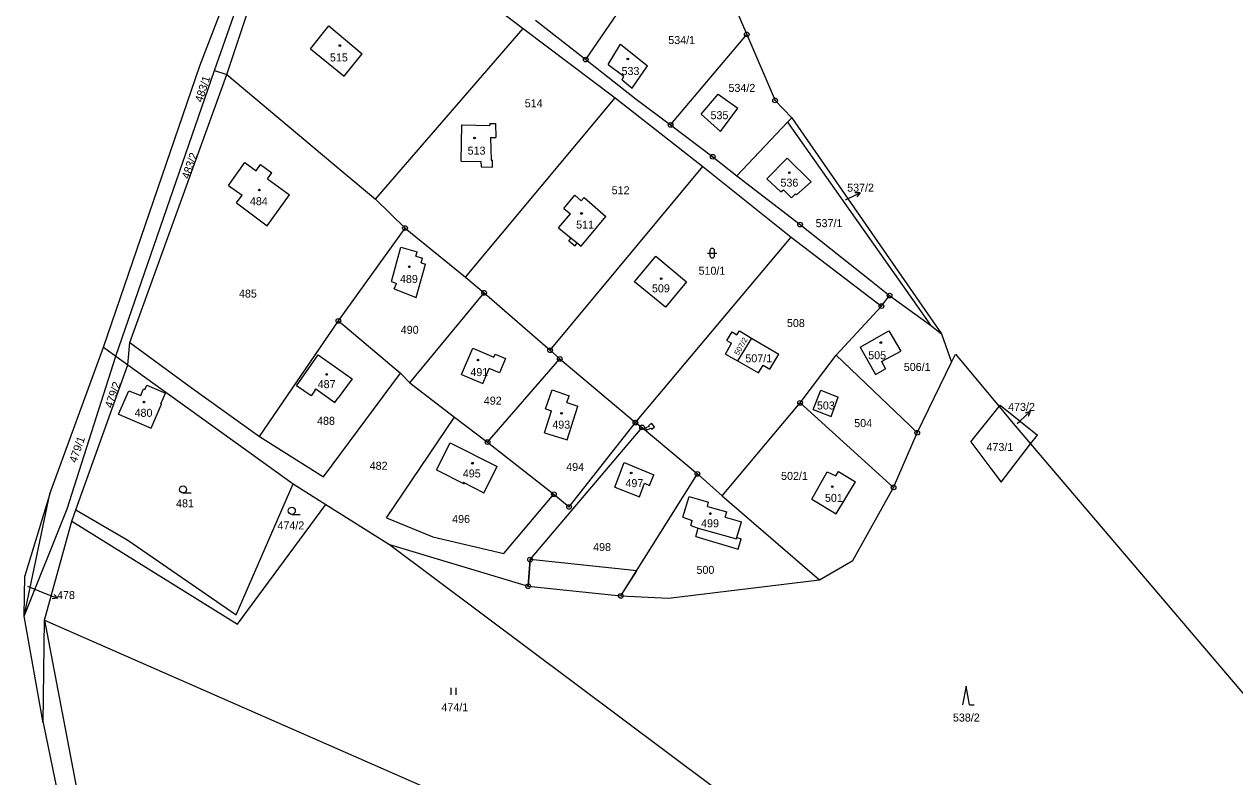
# Model space of a CAD drawing. Extents: x -633485 to -630509, y -1112692 to -1108818.
# Drawn here: x -633415.2 to -633158, y -1110845 to -1110685 of the extents above; entities that cross this region are included whole.
import ezdxf
from ezdxf.enums import TextEntityAlignment as Align

# ---------------------------------------------------------------- set-up
doc = ezdxf.new("R2010")
doc.units = 0
doc.header["$LTSCALE"] = 0.68
for name, color, linetype, lineweight in [('1', 7, 'Continuous', 25), ('13', 7, 'Continuous', 13), ('3', 7, 'Continuous', 25), ('4', 7, 'Continuous', 13), ('5', 7, 'Continuous', 25), ('7', 7, 'Continuous', 13), ('8', 7, 'Continuous', 25)]:
    doc.layers.add(name, color=color, linetype=linetype, lineweight=lineweight)
doc.layers.add('2', color=7, linetype='Continuous')

msp = doc.modelspace()

# ---------------------------------------------------------------- linework, layer by layer
at = {"layer": '1'}
for p, q in [((-633372.08, -1110695.76), (-633356.98, -1110649.71)), ((-633356.98, -1110649.71), (-633309.16, -1110685.92)), ((-633377.88, -1110693.9), (-633361.78, -1110652.1)), ((-633374.72, -1110694.91), (-633360.09, -1110653.04)), ((-633268.46, -1110671.42), (-633261.66, -1110687.22)), ((-633306.56, -1110684.16), (-633295.86, -1110692.55)), ((-633295.86, -1110692.55), (-633289.15, -1110682.83)), ((-633354.36, -1110690.24), (-633350.47, -1110685.42)), ((-633350.47, -1110685.42), (-633343.33, -1110691.37)), ((-633340.5, -1110722.24), (-633309.16, -1110685.92)), ((-633309.16, -1110685.92), (-633289.6, -1110700.65)), ((-633277.85, -1110706.44), (-633261.66, -1110687.22)), ((-633261.66, -1110687.22), (-633255.64, -1110701.22)), ((-633354.36, -1110690.24), (-633347.18, -1110696.1)), ((-633291.13, -1110693.6), (-633288.45, -1110689.27)), ((-633288.45, -1110689.27), (-633282.71, -1110693.89)), ((-633347.18, -1110696.1), (-633343.33, -1110691.37)), ((-633295.86, -1110692.55), (-633285.16, -1110700.94)), ((-633398.35, -1110753.67), (-633377.88, -1110693.9)), ((-633395.69, -1110755.6), (-633374.72, -1110694.91)), ((-633374.72, -1110694.91), (-633372.08, -1110695.76)), ((-633291.13, -1110693.6), (-633287.74, -1110696.09)), ((-633286.02, -1110698.62), (-633282.71, -1110693.89)), ((-633392.75, -1110752.65), (-633372.08, -1110695.76)), ((-633372.08, -1110695.76), (-633347.81, -1110716.11)), ((-633288.12, -1110696.86), (-633287.74, -1110696.09)), ((-633288.12, -1110696.86), (-633286.02, -1110698.62)), ((-633321.42, -1110738.77), (-633289.6, -1110700.65)), ((-633289.6, -1110700.65), (-633271, -1110715.31)), ((-633271.36, -1110704.17), (-633267.74, -1110699.87)), ((-633267.74, -1110699.87), (-633263.55, -1110702.89)), ((-633285.16, -1110700.94), (-633277.85, -1110706.44)), ((-633267.23, -1110707.82), (-633263.55, -1110702.89)), ((-633255.64, -1110701.22), (-633252.09, -1110704.91)), ((-633271.36, -1110704.17), (-633267.23, -1110707.82)), ((-633253, -1110705.88), (-633252.09, -1110704.91)), ((-633252.09, -1110704.91), (-633223.79, -1110745.72)), ((-633322.34, -1110714.16), (-633322.18, -1110706.45)), ((-633322.18, -1110706.45), (-633316.26, -1110706.57)), ((-633316.27, -1110706.17), (-633315.02, -1110706.14)), ((-633316.27, -1110706.17), (-633316.26, -1110706.57)), ((-633315.02, -1110706.14), (-633314.94, -1110709.11)), ((-633277.85, -1110706.44), (-633268.87, -1110713.2)), ((-633263.79, -1110717.29), (-633253, -1110705.88)), ((-633253, -1110705.88), (-633225.59, -1110744.76)), ((-633316.11, -1110709.14), (-633314.94, -1110709.11)), ((-633316.11, -1110709.14), (-633315.98, -1110713.91)), ((-633268.87, -1110713.2), (-633263.79, -1110717.29)), ((-633257.37, -1110717.92), (-633253.1, -1110713.53)), ((-633253.1, -1110713.53), (-633247.94, -1110718.54)), ((-633371.76, -1110719.28), (-633368.27, -1110714.46)), ((-633368.27, -1110714.46), (-633365.9, -1110716.17)), ((-633365.9, -1110716.17), (-633364.97, -1110714.88)), ((-633364.97, -1110714.88), (-633362.57, -1110716.63)), ((-633347.81, -1110716.11), (-633340.5, -1110722.24)), ((-633322.34, -1110714.16), (-633318.15, -1110714.21)), ((-633318.15, -1110714.21), (-633318.1, -1110715.35)), ((-633318.1, -1110715.35), (-633315.69, -1110715.42)), ((-633315.98, -1110713.91), (-633315.67, -1110713.91)), ((-633315.69, -1110715.42), (-633315.67, -1110713.91)), ((-633363.5, -1110717.91), (-633362.57, -1110716.63)), ((-633363.5, -1110717.91), (-633358.81, -1110721.31)), ((-633263.79, -1110717.29), (-633250.33, -1110727.62)), ((-633257.37, -1110717.92), (-633254.42, -1110720.64)), ((-633251.06, -1110721.31), (-633247.94, -1110718.54)), ((-633371.76, -1110719.28), (-633368.88, -1110721.36)), ((-633254.42, -1110720.64), (-633253.87, -1110720.23)), ((-633253.87, -1110720.23), (-633252.12, -1110721.92)), ((-633252.12, -1110721.92), (-633251.3, -1110721.08)), ((-633251.3, -1110721.08), (-633251.06, -1110721.31)), ((-633370.05, -1110722.98), (-633368.88, -1110721.36)), ((-633370.05, -1110722.98), (-633363.55, -1110727.86)), ((-633363.55, -1110727.86), (-633358.81, -1110721.31)), ((-633340.5, -1110722.24), (-633334.26, -1110728.37)), ((-633300.49, -1110724.19), (-633298.2, -1110721.39)), ((-633298.2, -1110721.39), (-633296.8, -1110722.58)), ((-633296.8, -1110722.58), (-633296.21, -1110721.88)), ((-633296.21, -1110721.88), (-633291.59, -1110725.87)), ((-633301.65, -1110728.31), (-633299.13, -1110725.34)), ((-633300.49, -1110724.19), (-633299.13, -1110725.34)), ((-633296.8, -1110732.23), (-633291.59, -1110725.87)), ((-633348.42, -1110748.09), (-633334.26, -1110728.37)), ((-633334.26, -1110728.37), (-633321.42, -1110738.77)), ((-633301.65, -1110728.31), (-633298.98, -1110730.47)), ((-633250.33, -1110727.62), (-633235.23, -1110739.6)), ((-633299.44, -1110731.05), (-633298.98, -1110730.47)), ((-633299.44, -1110731.05), (-633298.13, -1110732.1)), ((-633298.13, -1110732.1), (-633297.67, -1110731.53)), ((-633297.67, -1110731.53), (-633296.8, -1110732.23)), ((-633252.2, -1110730.26), (-633233.03, -1110744.95)), ((-633337.14, -1110739.7), (-633335.14, -1110732.43)), ((-633335.14, -1110732.43), (-633331.68, -1110733.42)), ((-633331.95, -1110734.35), (-633331.68, -1110733.42)), ((-633331.95, -1110734.35), (-633330.52, -1110734.76)), ((-633331.92, -1110743.08), (-633329.9, -1110736.02)), ((-633330.8, -1110735.76), (-633330.52, -1110734.76)), ((-633330.8, -1110735.76), (-633329.9, -1110736.02)), ((-633321.42, -1110738.77), (-633317.46, -1110742.12)), ((-633337.14, -1110739.7), (-633336.08, -1110740.12)), ((-633336.53, -1110741.29), (-633336.08, -1110740.12)), ((-633336.53, -1110741.29), (-633331.92, -1110743.08)), ((-633274.42, -1110739.78), (-633278.92, -1110745.2)), ((-633235.23, -1110739.6), (-633231.31, -1110742.7)), ((-633333.24, -1110761.26), (-633317.46, -1110742.12)), ((-633317.46, -1110742.12), (-633303.43, -1110754.31)), ((-633233.03, -1110744.95), (-633231.31, -1110742.7)), ((-633231.31, -1110742.7), (-633222.59, -1110749.02)), ((-633242.66, -1110755.33), (-633233.03, -1110744.95)), ((-633225.59, -1110744.76), (-633222.59, -1110749.02)), ((-633223.79, -1110745.72), (-633220.26, -1110750.82)), ((-633365.18, -1110772.63), (-633348.42, -1110748.09)), ((-633348.42, -1110748.09), (-633335.19, -1110759.18)), ((-633222.59, -1110749.02), (-633220.26, -1110750.82)), ((-633265.88, -1110752.27), (-633264.77, -1110750.41)), ((-633264.77, -1110750.41), (-633263.73, -1110751.01)), ((-633263.73, -1110751.01), (-633263.23, -1110750.18)), ((-633260.63, -1110751.72), (-633263.59, -1110756.6)), ((-633263.23, -1110750.18), (-633260.63, -1110751.72)), ((-633260.63, -1110751.72), (-633254.82, -1110755.17)), ((-633237.59, -1110753.65), (-633231.48, -1110750.17)), ((-633231.48, -1110750.17), (-633228.94, -1110754.53)), ((-633220.26, -1110750.82), (-633218.14, -1110756.82)), ((-633409.74, -1110784.84), (-633398.35, -1110753.67)), ((-633398.35, -1110753.67), (-633395.69, -1110755.6)), ((-633393.18, -1110757.41), (-633392.75, -1110752.65)), ((-633392.75, -1110752.65), (-633379.7, -1110762.27)), ((-633322.28, -1110759.49), (-633319.85, -1110753.89)), ((-633319.85, -1110753.89), (-633315.41, -1110755.82)), ((-633303.43, -1110754.31), (-633301.37, -1110756.17)), ((-633266.14, -1110755.13), (-633264.91, -1110752.84)), ((-633265.88, -1110752.27), (-633264.91, -1110752.84)), ((-633237.59, -1110753.65), (-633234.31, -1110759.45)), ((-633233.01, -1110756.74), (-633228.94, -1110754.53)), ((-633406.01, -1110788), (-633395.69, -1110755.6)), ((-633395.69, -1110755.6), (-633393.18, -1110757.41)), ((-633316.72, -1110773.84), (-633301.37, -1110756.17)), ((-633315.41, -1110755.82), (-633315.12, -1110755.13)), ((-633315.12, -1110755.13), (-633312.89, -1110756.06)), ((-633312.89, -1110756.06), (-633314.16, -1110759.09)), ((-633266.14, -1110755.13), (-633263.59, -1110756.6)), ((-633263.59, -1110756.6), (-633259.17, -1110759.13)), ((-633256.72, -1110758.37), (-633254.82, -1110755.17)), ((-633250.32, -1110765.5), (-633242.66, -1110755.33)), ((-633242.66, -1110755.33), (-633227.01, -1110770.33)), ((-633233.01, -1110756.74), (-633232.17, -1110758.24)), ((-633225.42, -1110771.85), (-633218.14, -1110756.82)), ((-633218.14, -1110756.82), (-633217.34, -1110755.18)), ((-633217.34, -1110755.18), (-633208.04, -1110766.3)), ((-633404.19, -1110788.25), (-633393.18, -1110757.41)), ((-633393.18, -1110757.41), (-633358.03, -1110782.72)), ((-633351.56, -1110781.21), (-633335.19, -1110759.18)), ((-633335.19, -1110759.18), (-633333.24, -1110761.26)), ((-633322.28, -1110759.49), (-633317.71, -1110761.37)), ((-633317.71, -1110761.37), (-633316.38, -1110758.17)), ((-633314.16, -1110759.09), (-633316.38, -1110758.17)), ((-633259.17, -1110759.13), (-633258.2, -1110757.49)), ((-633258.2, -1110757.49), (-633256.72, -1110758.37)), ((-633234.31, -1110759.45), (-633232.17, -1110758.24)), ((-633389.51, -1110762.67), (-633389.14, -1110761.74)), ((-633389.14, -1110761.74), (-633385.15, -1110763.42)), ((-633379.7, -1110762.27), (-633365.18, -1110772.63)), ((-633354.23, -1110764.02), (-633357.31, -1110761.87)), ((-633345.48, -1110760.42), (-633348.43, -1110764.42)), ((-633333.24, -1110761.26), (-633323.73, -1110768.53)), ((-633395.11, -1110767.93), (-633392.95, -1110762.91)), ((-633392.95, -1110762.91), (-633390.39, -1110763.94)), ((-633390.39, -1110763.94), (-633389.83, -1110762.54)), ((-633389.83, -1110762.54), (-633389.51, -1110762.67)), ((-633386.14, -1110765.74), (-633385.15, -1110763.42)), ((-633353.41, -1110762.84), (-633354.23, -1110764.02)), ((-633353.41, -1110762.84), (-633353.2, -1110762.54)), ((-633353.2, -1110762.54), (-633349.14, -1110765.4)), ((-633349.14, -1110765.4), (-633348.43, -1110764.42)), ((-633304.39, -1110766.8), (-633303.01, -1110762.75)), ((-633303.01, -1110762.75), (-633299.36, -1110764)), ((-633299.87, -1110765.44), (-633299.36, -1110764)), ((-633247.51, -1110766.91), (-633245.91, -1110762.82)), ((-633245.91, -1110762.82), (-633242.23, -1110764.26)), ((-633243.74, -1110768.38), (-633242.23, -1110764.26)), ((-633388.2, -1110770.9), (-633386.01, -1110765.8)), ((-633386.14, -1110765.74), (-633386.01, -1110765.8)), ((-633304.62, -1110771.84), (-633303.15, -1110767.19)), ((-633304.39, -1110766.8), (-633303.15, -1110767.19)), ((-633299.87, -1110765.44), (-633297.52, -1110766.17)), ((-633299.8, -1110773.34), (-633297.52, -1110766.17)), ((-633266.85, -1110785.22), (-633250.32, -1110765.5)), ((-633250.32, -1110765.5), (-633230.46, -1110783.45)), ((-633247.51, -1110766.91), (-633243.74, -1110768.38)), ((-633214.04, -1110773.79), (-633208.04, -1110766.3)), ((-633208.04, -1110766.3), (-633207.8, -1110766.01)), ((-633208.04, -1110766.3), (-633205.06, -1110769.86)), ((-633207.8, -1110766.01), (-633199.89, -1110772.35)), ((-633395.11, -1110767.93), (-633388.2, -1110770.9)), ((-633338.19, -1110789.94), (-633323.73, -1110768.53)), ((-633323.73, -1110768.53), (-633316.72, -1110773.84)), ((-633299.41, -1110787.62), (-633285.3, -1110769.7)), ((-633285.3, -1110769.7), (-633283.88, -1110770.71)), ((-633205.06, -1110769.86), (-633201.34, -1110774.23)), ((-633365.18, -1110772.63), (-633351.56, -1110781.21)), ((-633307.67, -1110798.79), (-633283.88, -1110770.71)), ((-633304.62, -1110771.84), (-633299.8, -1110773.34)), ((-633283.88, -1110770.71), (-633272.15, -1110780.61)), ((-633230.46, -1110783.45), (-633225.42, -1110771.85)), ((-633227.01, -1110770.33), (-633225.42, -1110771.85)), ((-633201.34, -1110774.23), (-633199.89, -1110772.35)), ((-633327.56, -1110779.71), (-633324.63, -1110773.96)), ((-633324.63, -1110773.96), (-633314.66, -1110779.05)), ((-633316.72, -1110773.84), (-633302.64, -1110784.91)), ((-633214.04, -1110773.79), (-633209.8, -1110779.42)), ((-633207.59, -1110782.36), (-633201.34, -1110774.23)), ((-633201.34, -1110774.23), (-633141.49, -1110844.6)), ((-633327.56, -1110779.71), (-633321.71, -1110782.69)), ((-633317.49, -1110784.62), (-633314.66, -1110779.05)), ((-633289.7, -1110783.43), (-633287.67, -1110778.17)), ((-633287.67, -1110778.17), (-633281.38, -1110780.76)), ((-633247.8, -1110785.98), (-633244.54, -1110780.14)), ((-633244.54, -1110780.14), (-633242.74, -1110781.02)), ((-633242.74, -1110781.02), (-633242.15, -1110780.07)), ((-633242.15, -1110780.07), (-633238.56, -1110782.28)), ((-633209.8, -1110779.42), (-633207.59, -1110782.36)), ((-633370.11, -1110810.53), (-633358.03, -1110782.72)), ((-633358.03, -1110782.72), (-633351.09, -1110787.09)), ((-633321.88, -1110782.32), (-633321.71, -1110782.69)), ((-633321.88, -1110782.32), (-633317.49, -1110784.62)), ((-633288.41, -1110806.53), (-633272.15, -1110780.61)), ((-633284.45, -1110785.45), (-633283.41, -1110782.57)), ((-633283.41, -1110782.57), (-633282.31, -1110783.03)), ((-633282.31, -1110783.03), (-633281.38, -1110780.76)), ((-633272.15, -1110780.61), (-633266.85, -1110785.22)), ((-633242.67, -1110789.08), (-633238.56, -1110782.28)), ((-633415.16, -1110810.8), (-633409.74, -1110784.84)), ((-633409.74, -1110784.84), (-633415.05, -1110802.23)), ((-633313.27, -1110797.49), (-633302.64, -1110784.91)), ((-633302.64, -1110784.91), (-633299.41, -1110787.62)), ((-633289.7, -1110783.43), (-633284.45, -1110785.45)), ((-633275.25, -1110789.81), (-633273.88, -1110785.37)), ((-633273.88, -1110785.37), (-633269.76, -1110786.61)), ((-633266.85, -1110785.22), (-633246.19, -1110803.08)), ((-633239.12, -1110799.01), (-633230.46, -1110783.45)), ((-633415.16, -1110810.8), (-633406.01, -1110788)), ((-633369.86, -1110812.49), (-633351.09, -1110787.09)), ((-633351.09, -1110787.09), (-633337.57, -1110795.62)), ((-633270.01, -1110787.49), (-633269.76, -1110786.61)), ((-633270.01, -1110787.49), (-633265.9, -1110788.67)), ((-633247.8, -1110785.98), (-633242.67, -1110789.08)), ((-633410.85, -1110811.65), (-633405.03, -1110790.61)), ((-633405.03, -1110790.61), (-633404.19, -1110788.25)), ((-633405.03, -1110790.61), (-633369.86, -1110812.49)), ((-633404.19, -1110788.25), (-633393.14, -1110794.71)), ((-633338.19, -1110789.94), (-633328.34, -1110794)), ((-633275.25, -1110789.81), (-633273.23, -1110790.52)), ((-633273.53, -1110791.58), (-633273.23, -1110790.52)), ((-633266.22, -1110789.78), (-633265.9, -1110788.67)), ((-633266.22, -1110789.78), (-633262.79, -1110790.78)), ((-633273.53, -1110791.58), (-633271.97, -1110792.1)), ((-633272.45, -1110793.87), (-633271.97, -1110792.1)), ((-633263.73, -1110794.09), (-633262.79, -1110790.78)), ((-633393.14, -1110794.71), (-633370.11, -1110810.53)), ((-633337.57, -1110795.62), (-633268.93, -1110846.94)), ((-633337.57, -1110795.62), (-633308.11, -1110804.46)), ((-633328.34, -1110794), (-633313.27, -1110797.49)), ((-633272.45, -1110793.87), (-633263.5, -1110796.62)), ((-633263.73, -1110794.09), (-633262.81, -1110794.37)), ((-633263.5, -1110796.62), (-633262.81, -1110794.37)), ((-633308.11, -1110804.46), (-633307.67, -1110798.79)), ((-633246.19, -1110803.08), (-633239.12, -1110799.01)), ((-633415.16, -1110810.8), (-633415.05, -1110802.23)), ((-633278.3, -1110806.98), (-633246.19, -1110803.08)), ((-633308.11, -1110804.46), (-633288.41, -1110806.53)), ((-633288.41, -1110806.53), (-633278.3, -1110806.98)), ((-633411.15, -1110833.49), (-633415.16, -1110810.8)), ((-633411.15, -1110833.49), (-633410.85, -1110811.65)), ((-633410.85, -1110811.65), (-633397.88, -1110879.52)), ((-633410.85, -1110811.65), (-633219.32, -1110895.7)), ((-633411.15, -1110833.49), (-633401.91, -1110878.32))]:
    msp.add_line(p, q, dxfattribs=at)
for points in [[(-633303.43, -1110754.31), (-633271, -1110715.31), (-633252.2, -1110730.26)], [(-633301.37, -1110756.17), (-633285.3, -1110769.7), (-633252.2, -1110730.26)], [(-633278.92, -1110745.2), (-633285.49, -1110739.8), (-633280.99, -1110734.34), (-633274.42, -1110739.78)], [(-633357.31, -1110761.87), (-633352.68, -1110755.3), (-633345.48, -1110760.42)]]:
    msp.add_lwpolyline(points, dxfattribs=at)
at = {"layer": '13'}
for points in [[(-633282.02, -1110770.91), (-633281.84, -1110771.1), (-633281.24, -1110770.58), (-633281.9, -1110769.82), (-633282.5, -1110770.35), (-633282.36, -1110770.51), (-633283.15, -1110770.82), (-633282.97, -1110771.28)], [(-633308.11, -1110804.46), (-633288.41, -1110806.53), (-633285.04, -1110801.16), (-633307.67, -1110798.79)]]:
    msp.add_lwpolyline(points, close=True, dxfattribs=at)
at = {"layer": '3'}
for p, q in [((-633269.991, -1110733.691), (-633267.989, -1110733.691)), ((-633269.491, -1110733.191), (-633269.491, -1110734.192)), ((-633268.489, -1110734.192), (-633268.489, -1110733.191)), ((-633381.413, -1110784.65), (-633379.663, -1110784.65)), ((-633358.313, -1110789.19), (-633356.563, -1110789.19)), ((-633324.421, -1110827.57), (-633324.421, -1110826.07)), ((-633323.42, -1110827.57), (-633323.42, -1110826.07)), ((-633214.32, -1110829.68), (-633213.324, -1110829.68))]:
    msp.add_line(p, q, dxfattribs=at)
msp.add_lwpolyline([(-633214.32, -1110829.68), (-633215.07, -1110825.68), (-633215.82, -1110829.68)], dxfattribs=at)
for centre in [(-633381.4129, -1110783.8998), (-633358.3129, -1110788.4398)]:
    msp.add_circle(centre, 0.75, dxfattribs=at)
for centre, start, end in [((-633268.99, -1110733.1909), 0, 180), ((-633268.99, -1110734.1909), 180, 359.98789)]:
    msp.add_arc(centre, 0.5, start, end, dxfattribs=at)
at = {"layer": '4'}
for p, q in [((-633298.98, -1110730.47), (-633297.67, -1110731.53)), ((-633271.97, -1110792.1), (-633263.81, -1110794.37)), ((-633263.81, -1110794.37), (-633263.73, -1110794.09))]:
    msp.add_line(p, q, dxfattribs=at)
at = {"layer": '5'}
for centre in [(-633348.0968, -1110689.5792), (-633286.9268, -1110692.4292), (-633319.4868, -1110709.2192), (-633252.6168, -1110716.5992), (-633365.1968, -1110720.2792), (-633296.7568, -1110725.2592), (-633333.3268, -1110736.5892), (-633279.8368, -1110739.0992), (-633233.1768, -1110752.6792), (-633318.7368, -1110756.4092), (-633350.8968, -1110759.4592), (-633389.7068, -1110765.3392), (-633301.0068, -1110767.7392), (-633319.9268, -1110778.3192), (-633286.2068, -1110780.3992), (-633243.4868, -1110783.3192), (-633269.3868, -1110789.0192)]:
    msp.add_circle(centre, 0.175, dxfattribs=at)
at = {"layer": '7'}
for p, q in [((-633237.56, -1110720.872), (-633238.679, -1110720.841)), ((-633201.465, -1110767.363), (-633202.539, -1110767.68)), ((-633408.088, -1110807.034), (-633408.828, -1110806.195))]:
    msp.add_line(p, q, dxfattribs=at)
for points in [[(-633240.67, -1110722.33), (-633240.28, -1110722.14), (-633237.56, -1110720.872), (-633238.256, -1110721.749)], [(-633204.18, -1110769.89), (-633203.66, -1110769.41), (-633201.465, -1110767.363), (-633201.856, -1110768.413)], [(-633414.46, -1110804.48), (-633410.87, -1110805.91), (-633408.088, -1110807.034), (-633409.204, -1110807.123)]]:
    msp.add_lwpolyline(points, dxfattribs=at)
at = {"layer": '8'}
for centre, radius in [((-633261.66, -1110687.2199), 0.5), ((-633261.66, -1110687.2199), 0.0303), ((-633295.86, -1110692.5499), 0.5), ((-633295.86, -1110692.5499), 0.0303), ((-633255.64, -1110701.2199), 0.5), ((-633255.64, -1110701.2199), 0.0303), ((-633277.85, -1110706.4399), 0.5), ((-633277.85, -1110706.4399), 0.0303), ((-633268.87, -1110713.1999), 0.5), ((-633268.87, -1110713.1999), 0.0303), ((-633334.26, -1110728.3699), 0.5), ((-633334.26, -1110728.3699), 0.0303), ((-633250.33, -1110727.6199), 0.5), ((-633250.33, -1110727.6199), 0.0303), ((-633317.46, -1110742.1199), 0.5), ((-633317.46, -1110742.1199), 0.0303), ((-633233.03, -1110744.9499), 0.5), ((-633231.31, -1110742.6999), 0.5), ((-633231.31, -1110742.6999), 0.0303), ((-633233.03, -1110744.9499), 0.0303), ((-633348.42, -1110748.0899), 0.5), ((-633348.42, -1110748.0899), 0.0303), ((-633303.43, -1110754.3099), 0.5), ((-633303.43, -1110754.3099), 0.0303), ((-633301.37, -1110756.1699), 0.5), ((-633301.37, -1110756.1699), 0.0303), ((-633250.32, -1110765.4999), 0.5), ((-633250.32, -1110765.4999), 0.0303), ((-633285.3, -1110769.6999), 0.5), ((-633285.3, -1110769.6999), 0.0303), ((-633283.88, -1110770.7099), 0.5), ((-633283.88, -1110770.7099), 0.0303), ((-633225.42, -1110771.8499), 0.5), ((-633225.42, -1110771.8499), 0.0303), ((-633316.72, -1110773.8399), 0.5), ((-633316.72, -1110773.8399), 0.0303), ((-633272.15, -1110780.6099), 0.5), ((-633272.15, -1110780.6099), 0.0303), ((-633230.46, -1110783.4499), 0.5), ((-633302.64, -1110784.9099), 0.5), ((-633302.64, -1110784.9099), 0.0303), ((-633230.46, -1110783.4499), 0.0303), ((-633299.41, -1110787.6199), 0.5), ((-633299.41, -1110787.6199), 0.0303), ((-633307.67, -1110798.7899), 0.5), ((-633307.67, -1110798.7899), 0.0303), ((-633308.11, -1110804.4599), 0.5), ((-633308.11, -1110804.4599), 0.0303), ((-633288.41, -1110806.5299), 0.5), ((-633288.41, -1110806.5299), 0.0303)]:
    msp.add_circle(centre, radius, dxfattribs=at)

# ---------------------------------------------------------------- texts
at = {"layer": '2'}
for s, p in [('534/1', (-633278.32, -1110689.265)), ('515', (-633350.21, -1110692.955)), ('533', (-633288.26, -1110695.835)), ('534/2', (-633265.53, -1110699.425)), ('514', (-633308.82, -1110702.695)), ('535', (-633269.35, -1110705.225)), ('513', (-633320.95, -1110712.755)), ('536', (-633254.49, -1110719.555)), ('512', (-633290.35, -1110721.175)), ('484', (-633367.21, -1110723.495)), ('537/1', (-633247.02, -1110728.165)), ('511', (-633297.9, -1110728.475)), ('489', (-633335.33, -1110740.025)), ('485', (-633369.53, -1110743.125)), ('509', (-633281.79, -1110742.015)), ('490', (-633335.16, -1110750.825)), ('508', (-633253.11, -1110749.385)), ('505', (-633235.85, -1110756.225)), ('506/1', (-633228.29, -1110758.715)), ('491', (-633320.37, -1110759.815)), ('487', (-633352.81, -1110762.375)), ('492', (-633317.51, -1110765.885)), ('480', (-633391.71, -1110768.465)), ('488', (-633352.94, -1110770.165)), ('493', (-633302.96, -1110770.965)), ('504', (-633238.82, -1110770.655)), ('473/1', (-633210.72, -1110775.725)), ('482', (-633341.76, -1110779.715)), ('495', (-633321.97, -1110781.345)), ('494', (-633300.01, -1110779.965)), ('502/1', (-633254.36, -1110781.865)), ('497', (-633287.42, -1110783.405)), ('501', (-633245.04, -1110786.535)), ('481', (-633382.89, -1110787.695)), ('474/2', (-633361.35, -1110792.405)), ('496', (-633324.24, -1110791.035)), ('499', (-633271.35, -1110791.935)), ('498', (-633294.29, -1110796.985)), ('500', (-633272.33, -1110801.835)), ('474/1', (-633326.52, -1110831.025)), ('538/2', (-633217.85, -1110833.215))]:
    msp.add_text(s, height=1.7, dxfattribs=at).set_placement(p)
for s, rotation, p in [('483/1', 72, (-633377.345, -1110701.771)), ('483/2', 71, (-633380.148, -1110718.068)), ('479/2', 71, (-633396.488, -1110766.758)), ('479/1', 71, (-633404.068, -1110778.368))]:
    msp.add_text(s, height=1.7, rotation=rotation, dxfattribs=at).set_placement(p)
for s, p in [('537/2', (-633237.48, -1110720.625)), ('510/1', (-633269.05, -1110738.272)), ('507/1', (-633259.1, -1110756.885)), ('503', (-633244.849, -1110766.905)), ('473/2', (-633203.28, -1110767.205)), ('478', (-633406.289, -1110807.195))]:
    msp.add_text(s, height=1.7, dxfattribs=at).set_placement(p, align=Align.CENTER)
at = {"layer": '2', "width": 1.05}
msp.add_text('507/2', height=1.139, rotation=60, dxfattribs=at).set_placement((-633262.4191, -1110753.7562), align=Align.CENTER)

doc.saveas('drawing.dxf')
